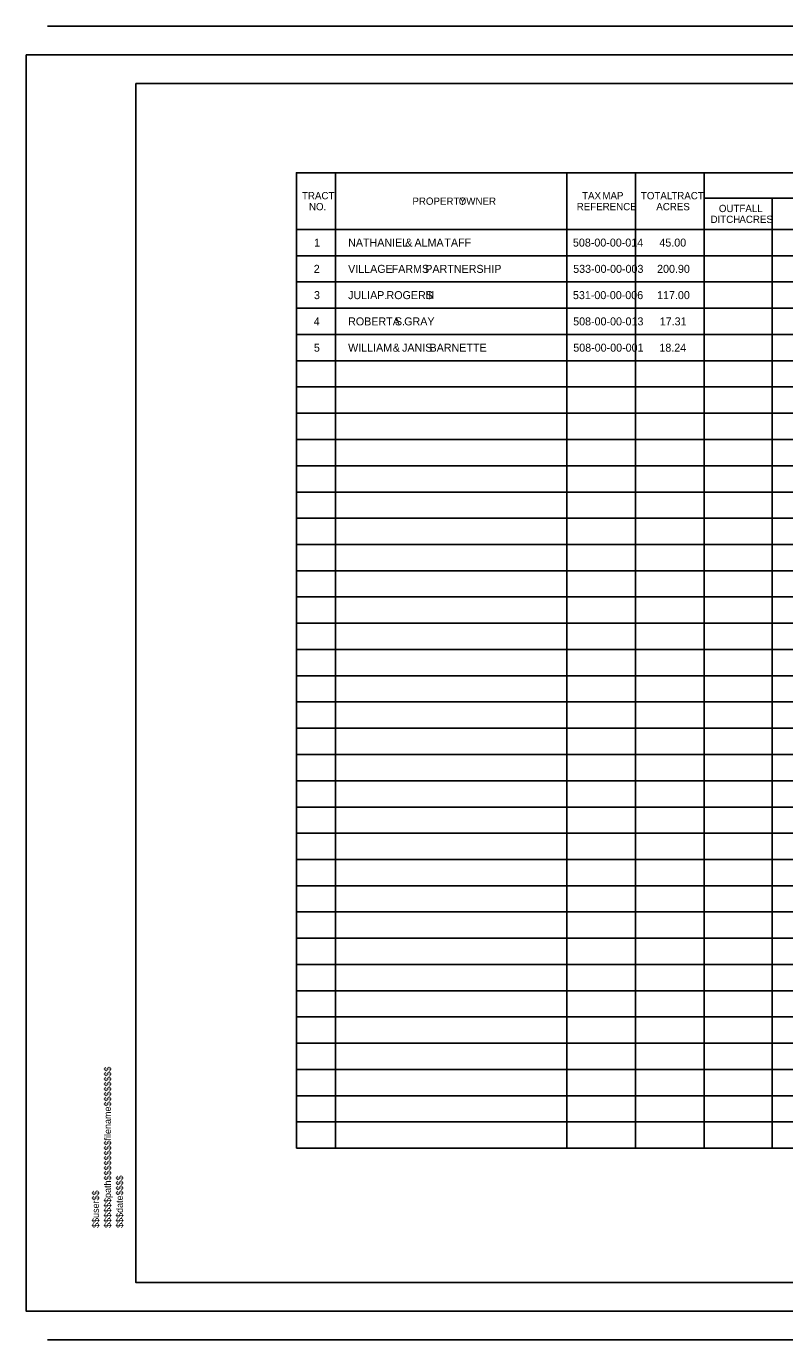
# Model space of a CAD drawing. Extents: x 9981 to 11777, y 9975 to 11125.
# Drawn here: x 9981 to 10646, y 9975 to 11125 of the extents above; entities that cross this region are included whole.
import ezdxf

# ---------------------------------------------------------------- set-up
doc = ezdxf.new("R2010")
doc.units = 0
for name, color, linetype in [('Default', 7, 'Continuous'), ('RD_SHT_Bndy', 7, 'Continuous'), ('RD_SHT_ID', 7, 'Continuous'), ('RD_SHT_IplotShp', 7, 'Continuous'), ('RD_SHT_MjGrid', 7, 'Continuous'), ('RD_TX_RW', 7, 'Continuous')]:
    doc.layers.add(name, color=color, linetype=linetype)

msp = doc.modelspace()

# ---------------------------------------------------------------- linework, layer by layer
at = {"layer": 'Default'}
msp.add_line((10218, 10996.8), (10218, 10996.8), dxfattribs=at)
at = {"layer": 'RD_SHT_Bndy'}
for p, q in [((10000, 11125), (11760, 11125)), ((10000, 11100), (11760, 11100)), ((10000, 10000), (11760, 10000)), ((10000, 9975), (11760, 9975))]:
    msp.add_line(p, q, dxfattribs=at)
for points in [[(10077.4, 11075), (11752.4, 11075), (11752.4, 10025), (10077.4, 10025)], [(10218, 10142.7), (11560.9, 10142.7), (11560.9, 10996.8), (10218, 10996.8)]]:
    msp.add_lwpolyline(points, close=True, dxfattribs=at)
at = {"layer": 'RD_SHT_IplotShp'}
msp.add_lwpolyline([(9981.4, 11100), (11777.4, 11100), (11777.4, 10000), (9981.4, 10000)], close=True, dxfattribs=at)
at = {"layer": 'RD_SHT_MjGrid'}
for p, q in [((10218, 10996.8), (11560.9, 10996.8)), ((10218, 10142.7), (10218, 10996.8)), ((10252.2, 10142.7), (10252.2, 10996.8)), ((10454.7, 10142.7), (10454.7, 10996.8)), ((10514.9, 10142.7), (10514.9, 10996.8)), ((10575.2, 10142.7), (10575.2, 10996.8)), ((10575.2, 10974.4), (10813.7, 10974.4)), ((10634.8, 10142.7), (10634.8, 10974.4)), ((10218, 10947.1), (11560.9, 10947.1)), ((10218, 10924.1), (11560.9, 10924.1)), ((10218, 10901.1), (11560.9, 10901.1)), ((10218, 10878.1), (11560.9, 10878.1)), ((10218, 10855.1), (11560.9, 10855.1)), ((10218, 10832.1), (11560.9, 10832.1)), ((10218, 10809.2), (11560.9, 10809.2)), ((10218, 10786.2), (11560.9, 10786.2)), ((10218, 10763.2), (11560.9, 10763.2)), ((10218, 10740.2), (11560.9, 10740.2)), ((10218, 10717.2), (11560.9, 10717.2)), ((10218, 10694.3), (11560.9, 10694.3)), ((10218, 10671.3), (11560.9, 10671.3)), ((10218, 10648.3), (11560.9, 10648.3)), ((10218, 10625.3), (11560.9, 10625.3)), ((10218, 10602.3), (11560.9, 10602.3)), ((10218, 10579.3), (11560.9, 10579.3)), ((10218, 10556.4), (11560.9, 10556.4)), ((10218, 10533.4), (11560.9, 10533.4)), ((10218, 10510.4), (11560.9, 10510.4)), ((10218, 10487.4), (11560.9, 10487.4)), ((10218, 10464.4), (11560.9, 10464.4)), ((10218, 10441.4), (11560.9, 10441.4)), ((10218, 10418.5), (11560.9, 10418.5)), ((10218, 10395.5), (11560.9, 10395.5)), ((10218, 10372.5), (11560.9, 10372.5)), ((10218, 10349.5), (11560.9, 10349.5)), ((10218, 10326.5), (11560.9, 10326.5)), ((10218, 10303.6), (11560.9, 10303.6)), ((10218, 10280.6), (11560.9, 10280.6)), ((10218, 10257.6), (11560.9, 10257.6)), ((10218, 10234.6), (11560.9, 10234.6)), ((10218, 10211.6), (11560.9, 10211.6)), ((10218, 10188.6), (11560.9, 10188.6)), ((10218, 10165.7), (11560.9, 10165.7)), ((10218, 10142.7), (11560.9, 10142.7))]:
    msp.add_line(p, q, dxfattribs=at)

# ---------------------------------------------------------------- texts
at = {"layer": 'RD_SHT_ID'}
for s, p in [('$$$$$$path$$$$$$$$filename$$$$$$$$', (10055.6, 10072.9)), ('$$$date$$$$', (10066.1, 10072.9)), ('$$user$$', (10045.1, 10072.9))]:
    msp.add_text(s, height=5.88, rotation=90, dxfattribs=at).set_placement(p)
at = {"layer": 'RD_TX_RW'}
for s, height, p in [('TRACT', 6.37, (10222.9, 10973.5)), ('PROPERTY', 6.37, (10319.6, 10968.7)), (' OWNER', 6.37, (10357.8, 10968.7)), ('TAX', 6.37, (10468.2, 10973.5)), (' MAP', 6.37, (10483.6, 10973.5)), ('TOTAL', 6.37, (10519.7, 10973.5)), (' TRACT', 6.37, (10544, 10973.5)), ('NO.', 6.37, (10229, 10963.9)), ('REFERENCE', 6.37, (10463.5, 10963.9)), ('ACRES', 6.37, (10533.2, 10963.9)), ('OUTFALL', 6.37, (10588, 10962.3)), ('DITCH', 6.37, (10580.7, 10952.8)), (' ACRES', 6.37, (10603.6, 10952.8)), ('1', 7.01, (10233.5, 10932.1)), ('NATHANIEL', 7.01, (10263.3, 10932.1)), (' &', 7.01, (10310.7, 10932.1)), (' ALMA', 7.01, (10318.8, 10932.1)), (' TAFF', 7.01, (10345, 10932.1)), ('508-00-00-014', 7.008, (10460.2, 10932.1)), ('45.00', 7.01, (10535.9, 10932.1)), ('2', 7.01, (10233.2, 10909.1)), ('VILLAGE', 7.01, (10263.3, 10909.1)), (' FARMS', 7.01, (10298.8, 10909.1)), (' PARTNERSHIP', 7.008, (10328.3, 10909.1)), ('533-00-00-003', 7.008, (10460.4, 10909.1)), ('200.90', 7.01, (10533.9, 10909.1)), ('3', 7.01, (10233.4, 10886.1)), ('JULIA', 7.01, (10263.3, 10886.1)), (' P.', 7.01, (10286.1, 10886.1)), (' ROGERS', 7.01, (10294.3, 10886.1)), (' III', 7.01, (10328.3, 10886.1)), ('531-00-00-006', 7.008, (10460.2, 10886.1)), ('117.00', 7.01, (10533.9, 10886.1)), ('4', 7.01, (10233.2, 10863.1)), ('ROBERTA', 7.01, (10263.3, 10863.1)), (' S.', 7.01, (10301.7, 10863.1)), (' GRAY', 7.01, (10309.8, 10863.1)), ('508-00-00-013', 7.008, (10460.4, 10863.1)), ('17.31', 7.01, (10536.2, 10863.1)), ('5', 7.01, (10233.3, 10840.1)), ('WILLIAM', 7.01, (10263.3, 10840.1)), (' &', 7.01, (10299.8, 10840.1)), (' JANIS', 7.01, (10307.9, 10840.1)), (' BARNETTE', 7.01, (10332, 10840.1)), ('508-00-00-001', 7.008, (10460.5, 10840.1)), ('18.24', 7.01, (10535.9, 10840.1))]:
    msp.add_text(s, height=height, dxfattribs=at).set_placement(p)

doc.saveas('drawing.dxf')
